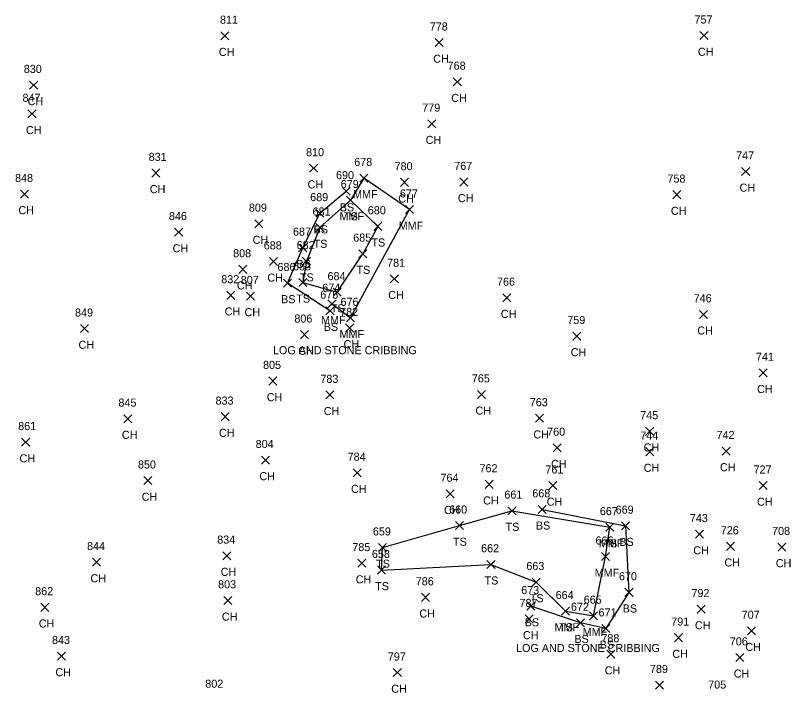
# Model space of a CAD drawing. Extents: x 1885914 to 1887218, y 756253 to 760620.
# Drawn here: x 1886841 to 1887033.2, y 759954.5 to 760121.7 of the extents above; entities that cross this region are included whole.
import ezdxf

# ---------------------------------------------------------------- set-up
doc = ezdxf.new("R2010")
doc.units = 0
for name, color, linetype in [('L_A', 7, 'Continuous'), ('L_C', 7, 'Continuous'), ('L_I', 7, 'Continuous'), ('L_TIC', 7, 'Continuous'), ('LDEFAULT', 7, 'Continuous'), ('LELB', 7, 'Continuous')]:
    doc.layers.add(name, color=color, linetype=linetype)

msp = doc.modelspace()

# ---------------------------------------------------------------- linework, layer by layer
at = {"layer": 'L_TIC'}
for points in [[(1887010.77, 760115.74), (1887012.77, 760117.74)], [(1887012.77, 760115.74), (1887010.77, 760117.74)], [(1886891.98, 760115.7), (1886893.98, 760117.7)], [(1886893.98, 760115.7), (1886891.98, 760117.7)], [(1886945.13, 760114.01), (1886947.13, 760116.01)], [(1886947.13, 760114.01), (1886945.13, 760116.01)], [(1886949.61, 760104.28), (1886951.61, 760106.28)], [(1886951.61, 760104.28), (1886949.61, 760106.28)], [(1886844.55, 760103.48), (1886846.55, 760105.48)], [(1886846.55, 760103.48), (1886844.55, 760105.48)], [(1886844.14, 760096.31), (1886846.14, 760098.31)], [(1886846.14, 760096.31), (1886844.14, 760098.31)], [(1886943.27, 760093.87), (1886945.27, 760095.87)], [(1886945.27, 760093.87), (1886943.27, 760095.87)], [(1886874.87, 760081.65), (1886876.87, 760083.65)], [(1886876.87, 760081.65), (1886874.87, 760083.65)], [(1886913.98, 760082.82), (1886915.98, 760084.82)], [(1886915.98, 760082.82), (1886913.98, 760084.82)], [(1887021.1, 760082.02), (1887023.1, 760084.02)], [(1887023.1, 760082.02), (1887021.1, 760084.02)], [(1886926.45, 760080.4), (1886928.45, 760082.4)], [(1886928.45, 760080.4), (1886926.45, 760082.4)], [(1886936.5, 760079.33), (1886938.5, 760081.33)], [(1886938.5, 760079.33), (1886936.5, 760081.33)], [(1886951.25, 760079.42), (1886953.25, 760081.42)], [(1886953.25, 760079.42), (1886951.25, 760081.42)], [(1886842.29, 760076.43), (1886844.29, 760078.43)], [(1886844.29, 760076.43), (1886842.29, 760078.43)], [(1886922.01, 760077.13), (1886924.01, 760079.13)], [(1886924.01, 760077.13), (1886922.01, 760079.13)], [(1887004.07, 760076.27), (1887006.07, 760078.27)], [(1887006.07, 760076.27), (1887004.07, 760078.27)], [(1886923.1, 760074.91), (1886925.1, 760076.91)], [(1886925.1, 760074.91), (1886923.1, 760076.91)], [(1886923.1, 760074.91), (1886925.1, 760076.91)], [(1886925.1, 760074.91), (1886923.1, 760076.91)], [(1886923.1, 760074.91), (1886925.1, 760076.91)], [(1886925.1, 760074.91), (1886923.1, 760076.91)], [(1886915.53, 760071.66), (1886917.53, 760073.66)], [(1886917.53, 760071.66), (1886915.53, 760073.66)], [(1886937.78, 760072.57), (1886939.78, 760074.57)], [(1886939.78, 760072.57), (1886937.78, 760074.57)], [(1886900.37, 760069.06), (1886902.37, 760071.06)], [(1886902.37, 760069.06), (1886900.37, 760071.06)], [(1886915.55, 760068.09), (1886917.55, 760070.09)], [(1886917.55, 760068.09), (1886915.55, 760070.09)], [(1886929.89, 760068.41), (1886931.89, 760070.41)], [(1886931.89, 760068.41), (1886929.89, 760070.41)], [(1886880.51, 760066.97), (1886882.51, 760068.97)], [(1886882.51, 760066.97), (1886880.51, 760068.97)], [(1886911.26, 760063.1), (1886913.26, 760065.1)], [(1886913.26, 760063.1), (1886911.26, 760065.1)], [(1886926.2, 760061.62), (1886928.2, 760063.62)], [(1886928.2, 760061.62), (1886926.2, 760063.62)], [(1886926.2, 760061.62), (1886928.2, 760063.62)], [(1886928.2, 760061.62), (1886926.2, 760063.62)], [(1886904.01, 760059.69), (1886906.01, 760061.69)], [(1886906.01, 760059.69), (1886904.01, 760061.69)], [(1886912.17, 760059.76), (1886914.17, 760061.76)], [(1886914.17, 760059.76), (1886912.17, 760061.76)], [(1886896.45, 760057.75), (1886898.45, 760059.75)], [(1886898.45, 760057.75), (1886896.45, 760059.75)], [(1886907.47, 760054.34), (1886909.47, 760056.34)], [(1886909.47, 760054.34), (1886907.47, 760056.34)], [(1886911.27, 760054.48), (1886913.27, 760056.48)], [(1886913.27, 760054.48), (1886911.27, 760056.48)], [(1886933.99, 760055.39), (1886935.99, 760057.39)], [(1886935.99, 760055.39), (1886933.99, 760057.39)], [(1886893.43, 760051.3), (1886895.43, 760053.3)], [(1886895.43, 760051.3), (1886893.43, 760053.3)], [(1886898.34, 760051.11), (1886900.34, 760053.11)], [(1886900.34, 760051.11), (1886898.34, 760053.11)], [(1886919.82, 760052.05), (1886921.82, 760054.05)], [(1886921.82, 760052.05), (1886919.82, 760054.05)], [(1886961.91, 760050.69), (1886963.91, 760052.69)], [(1886963.91, 760050.69), (1886961.91, 760052.69)], [(1886918.53, 760049.2), (1886920.53, 760051.2)], [(1886920.53, 760049.2), (1886918.53, 760051.2)], [(1886918.03, 760047.47), (1886920.03, 760049.47)], [(1886920.03, 760047.47), (1886918.03, 760049.47)], [(1886918.03, 760047.47), (1886920.03, 760049.47)], [(1886920.03, 760047.47), (1886918.03, 760049.47)], [(1887010.62, 760046.57), (1887012.62, 760048.57)], [(1887012.62, 760046.57), (1887010.62, 760048.57)], [(1886923.11, 760045.68), (1886925.11, 760047.68)], [(1886925.11, 760045.68), (1886923.11, 760047.68)], [(1886857.18, 760043.03), (1886859.18, 760045.03)], [(1886859.18, 760043.03), (1886857.18, 760045.03)], [(1886922.91, 760043.19), (1886924.91, 760045.19)], [(1886924.91, 760043.19), (1886922.91, 760045.19)], [(1886911.68, 760041.53), (1886913.68, 760043.53)], [(1886913.68, 760041.53), (1886911.68, 760043.53)], [(1886979.25, 760041.18), (1886981.25, 760043.18)], [(1886981.25, 760041.18), (1886979.25, 760043.18)], [(1887025.45, 760032.05), (1887027.45, 760034.05)], [(1887027.45, 760032.05), (1887025.45, 760034.05)], [(1886903.87, 760030.03), (1886905.87, 760032.03)], [(1886905.87, 760030.03), (1886903.87, 760032.03)], [(1886918, 760026.57), (1886920, 760028.57)], [(1886920, 760026.57), (1886918, 760028.57)], [(1886955.62, 760026.69), (1886957.62, 760028.69)], [(1886957.62, 760026.69), (1886955.62, 760028.69)], [(1886867.93, 760020.68), (1886869.93, 760022.68)], [(1886869.93, 760020.68), (1886867.93, 760022.68)], [(1886892.02, 760021.18), (1886894.02, 760023.18)], [(1886894.02, 760021.18), (1886892.02, 760023.18)], [(1886969.99, 760020.78), (1886971.99, 760022.78)], [(1886971.99, 760020.78), (1886969.99, 760022.78)], [(1886997.31, 760017.55), (1886999.31, 760019.55)], [(1886999.31, 760017.55), (1886997.31, 760019.55)], [(1886842.56, 760014.85), (1886844.56, 760016.85)], [(1886844.56, 760014.85), (1886842.56, 760016.85)], [(1886974.38, 760013.46), (1886976.38, 760015.46)], [(1886976.38, 760013.46), (1886974.38, 760015.46)], [(1886997.34, 760012.5), (1886999.34, 760014.5)], [(1886999.34, 760012.5), (1886997.34, 760014.5)], [(1887016.24, 760012.64), (1887018.24, 760014.64)], [(1887018.24, 760012.64), (1887016.24, 760014.64)], [(1886902.04, 760010.41), (1886904.04, 760012.41)], [(1886904.04, 760010.41), (1886902.04, 760012.41)], [(1886924.78, 760007.26), (1886926.78, 760009.26)], [(1886926.78, 760007.26), (1886924.78, 760009.26)], [(1886872.85, 760005.32), (1886874.85, 760007.32)], [(1886874.85, 760005.32), (1886872.85, 760007.32)], [(1886957.52, 760004.39), (1886959.52, 760006.39)], [(1886959.52, 760004.39), (1886957.52, 760006.39)], [(1886973.29, 760004.08), (1886975.29, 760006.08)], [(1886975.29, 760004.08), (1886973.29, 760006.08)], [(1887025.43, 760004.08), (1887027.43, 760006.08)], [(1887027.43, 760004.08), (1887025.43, 760006.08)], [(1886947.84, 760002.03), (1886949.84, 760004.03)], [(1886949.84, 760002.03), (1886947.84, 760004.03)], [(1886963.16, 759997.85), (1886965.16, 759999.85)], [(1886965.16, 759997.85), (1886963.16, 759999.85)], [(1886970.65, 759998.17), (1886972.65, 760000.17)], [(1886972.65, 759998.17), (1886970.65, 760000.17)], [(1886950.13, 759994.15), (1886952.13, 759996.15)], [(1886952.13, 759994.15), (1886950.13, 759996.15)], [(1886987.41, 759993.74), (1886989.41, 759995.74)], [(1886989.41, 759993.74), (1886987.41, 759995.74)], [(1886987.41, 759993.74), (1886989.41, 759995.74)], [(1886989.41, 759993.74), (1886987.41, 759995.74)], [(1886991.33, 759994.11), (1886993.33, 759996.11)], [(1886993.33, 759994.11), (1886991.33, 759996.11)], [(1887009.63, 759992.02), (1887011.63, 759994.02)], [(1887011.63, 759992.02), (1887009.63, 759994.02)], [(1887017.35, 759989.01), (1887019.35, 759991.01)], [(1887019.35, 759989.01), (1887017.35, 759991.01)], [(1886931.08, 759988.71), (1886933.08, 759990.71)], [(1886933.08, 759988.71), (1886931.08, 759990.71)], [(1887030.09, 759988.83), (1887032.09, 759990.83)], [(1887032.09, 759988.83), (1887030.09, 759990.83)], [(1886860.15, 759985.08), (1886862.15, 759987.08)], [(1886862.15, 759985.08), (1886860.15, 759987.08)], [(1886892.43, 759986.68), (1886894.43, 759988.68)], [(1886894.43, 759986.68), (1886892.43, 759988.68)], [(1886986.38, 759986.46), (1886988.38, 759988.46)], [(1886988.38, 759986.46), (1886986.38, 759988.46)], [(1886925.93, 759984.82), (1886927.93, 759986.82)], [(1886927.93, 759984.82), (1886925.93, 759986.82)], [(1886930.83, 759983.13), (1886932.83, 759985.13)], [(1886932.83, 759983.13), (1886930.83, 759985.13)], [(1886930.83, 759983.13), (1886932.83, 759985.13)], [(1886932.83, 759983.13), (1886930.83, 759985.13)], [(1886957.95, 759984.53), (1886959.95, 759986.53)], [(1886959.95, 759984.53), (1886957.95, 759986.53)], [(1886969.18, 759980.13), (1886971.18, 759982.13)], [(1886971.18, 759980.13), (1886969.18, 759982.13)], [(1886992.17, 759977.59), (1886994.17, 759979.59)], [(1886994.17, 759977.59), (1886992.17, 759979.59)], [(1886892.72, 759975.58), (1886894.72, 759977.58)], [(1886894.72, 759975.58), (1886892.72, 759977.58)], [(1886941.71, 759976.35), (1886943.71, 759978.35)], [(1886943.71, 759976.35), (1886941.71, 759978.35)], [(1886847.34, 759973.87), (1886849.34, 759975.87)], [(1886849.34, 759973.87), (1886847.34, 759975.87)], [(1886967.86, 759974.15), (1886969.86, 759976.15)], [(1886969.86, 759974.15), (1886967.86, 759976.15)], [(1886976.44, 759972.93), (1886978.44, 759974.93)], [(1886978.44, 759972.93), (1886976.44, 759974.93)], [(1886976.44, 759972.93), (1886978.44, 759974.93)], [(1886978.44, 759972.93), (1886976.44, 759974.93)], [(1886983.39, 759971.78), (1886985.39, 759973.78)], [(1886985.39, 759971.78), (1886983.39, 759973.78)], [(1887010.04, 759973.41), (1887012.04, 759975.41)], [(1887012.04, 759973.41), (1887010.04, 759975.41)], [(1886967.39, 759970.97), (1886969.39, 759972.97)], [(1886969.39, 759970.97), (1886967.39, 759972.97)], [(1886980.18, 759970.02), (1886982.18, 759972.02)], [(1886982.18, 759970.02), (1886980.18, 759972.02)], [(1886986.46, 759968.61), (1886988.46, 759970.61)], [(1886988.46, 759968.61), (1886986.46, 759970.61)], [(1887022.56, 759968.04), (1887024.56, 759970.04)], [(1887024.56, 759968.04), (1887022.56, 759970.04)], [(1887004.44, 759966.34), (1887006.44, 759968.34)], [(1887006.44, 759966.34), (1887004.44, 759968.34)], [(1886987.69, 759962.23), (1886989.69, 759964.23)], [(1886989.69, 759962.23), (1886987.69, 759964.23)], [(1886851.46, 759961.77), (1886853.46, 759963.77)], [(1886853.46, 759961.77), (1886851.46, 759963.77)], [(1887019.66, 759961.43), (1887021.66, 759963.43)], [(1887021.66, 759961.43), (1887019.66, 759963.43)], [(1886934.73, 759957.67), (1886936.73, 759959.67)], [(1886936.73, 759957.67), (1886934.73, 759959.67)], [(1886999.74, 759954.58), (1887001.74, 759956.58)], [(1887001.74, 759954.58), (1886999.74, 759956.58)]]:
    msp.add_lwpolyline(points, dxfattribs=at)
at = {"layer": 'LDEFAULT'}
for points in [[(1886919.53, 760050.2), (1886924.11, 760046.68), (1886938.78, 760073.57), (1886927.45, 760081.4), (1886924.1, 760075.91)], [(1886977.44, 759973.93), (1886984.39, 759972.78), (1886987.38, 759987.46), (1886988.41, 759994.74)]]:
    msp.add_lwpolyline(points, dxfattribs=at)
at = {"layer": 'LELB'}
for points in [[(1886919.03, 760048.47), (1886908.47, 760055.34), (1886912.26, 760064.1), (1886916.53, 760072.66), (1886923.01, 760078.13)], [(1886924.1, 760075.91), (1886916.55, 760069.09), (1886913.17, 760060.76), (1886912.27, 760055.48), (1886920.82, 760053.05), (1886927.2, 760062.62)], [(1886924.1, 760075.91), (1886930.89, 760069.41), (1886927.2, 760062.62)], [(1886931.83, 759984.13), (1886932.08, 759989.71), (1886951.13, 759995.15), (1886964.16, 759998.85), (1886988.41, 759994.74)], [(1886971.65, 759999.17), (1886992.33, 759995.11), (1886993.17, 759978.59), (1886987.46, 759969.61), (1886981.18, 759971.02), (1886968.86, 759975.15)], [(1886931.83, 759984.13), (1886958.95, 759985.53), (1886970.18, 759981.13), (1886977.44, 759973.93)]]:
    msp.add_lwpolyline(points, dxfattribs=at)

# ---------------------------------------------------------------- texts
at = {"layer": 'L_A'}
for s, p in [('CH', (1886891.47, 760111.7)), ('CH', (1886944.62, 760110.01)), ('CH', (1887010.26, 760111.74)), ('CH', (1886844.04, 760099.48)), ('CH', (1886949.1, 760100.28)), ('CH', (1886843.63, 760092.31)), ('CH', (1886942.75, 760089.87)), ('CH', (1886874.35, 760077.65)), ('CH', (1886913.47, 760078.82)), ('CH', (1887020.59, 760078.02)), ('MMF', (1886924.74, 760076.4)), ('CH', (1886950.74, 760075.42)), ('CH', (1886935.98, 760075.33)), ('CH', (1886841.78, 760072.43)), ('BS', (1886921.45, 760073.13)), ('CH', (1887003.56, 760072.27)), ('MMF', (1886921.39, 760070.91)), ('TS', (1886922.51, 760070.91)), ('TS', (1886922.51, 760070.91)), ('BS', (1886914.97, 760067.66)), ('MMF', (1886936.06, 760068.57)), ('CH', (1886899.86, 760065.06)), ('TS', (1886914.96, 760064.09)), ('TS', (1886929.3, 760064.41)), ('CH', (1886880, 760062.97)), ('BS', (1886910.7, 760059.1)), ('TS', (1886925.61, 760057.62)), ('TS', (1886925.61, 760057.62)), ('CH', (1886903.5, 760055.69)), ('TS', (1886911.58, 760055.76)), ('CH', (1886895.94, 760053.75)), ('TS', (1886910.68, 760050.48)), ('CH', (1886933.48, 760051.39)), ('BS', (1886906.91, 760050.34)), ('CH', (1886892.92, 760047.3)), ('CH', (1886897.83, 760047.11)), ('TS', (1886919.23, 760048.05)), ('CH', (1886961.4, 760046.69)), ('MMF', (1886916.81, 760045.2)), ('BS', (1886917.47, 760043.47)), ('BS', (1886917.47, 760043.47)), ('MMF', (1886921.4, 760041.68)), ('CH', (1887010.11, 760042.57)), ('CH', (1886856.67, 760039.03)), ('CH', (1886922.4, 760039.19)), ('CH', (1886911.17, 760037.53)), ('CH', (1886978.74, 760037.18)), ('CH', (1887024.93, 760028.05)), ('CH', (1886903.36, 760026.03)), ('CH', (1886917.49, 760022.57)), ('CH', (1886955.11, 760022.69)), ('CH', (1886867.42, 760016.68)), ('CH', (1886891.5, 760017.18)), ('CH', (1886969.48, 760016.78)), ('CH', (1886996.8, 760013.55)), ('CH', (1886842.04, 760010.85)), ('CH', (1886973.86, 760009.46)), ('CH', (1886996.83, 760008.5)), ('CH', (1887015.73, 760008.64)), ('CH', (1886901.53, 760006.41)), ('CH', (1886924.26, 760003.26)), ('CH', (1886872.34, 760001.32)), ('CH', (1886957.01, 760000.39)), ('CH', (1886972.77, 760000.08)), ('CH', (1887024.92, 760000.08)), ('CH', (1886947.32, 759998.03)), ('TS', (1886962.57, 759993.85)), ('BS', (1886970.09, 759994.17)), ('TS', (1886949.54, 759990.15)), ('MMF', (1886985.69, 759989.74)), ('TS', (1886986.82, 759989.74)), ('BS', (1886990.77, 759990.11)), ('CH', (1887009.12, 759988.02)), ('TS', (1886930.49, 759984.71)), ('CH', (1887016.84, 759985.01)), ('CH', (1887029.58, 759984.83)), ('CH', (1886891.92, 759982.68)), ('MMF', (1886984.66, 759982.46)), ('CH', (1886859.64, 759981.08)), ('CH', (1886925.42, 759980.82)), ('TS', (1886957.36, 759980.53)), ('TS', (1886930.23, 759979.13)), ('TS', (1886930.23, 759979.13)), ('TS', (1886968.59, 759976.13)), ('BS', (1886991.61, 759973.59)), ('CH', (1886892.21, 759971.58)), ('CH', (1886941.2, 759972.35)), ('CH', (1886846.82, 759969.87)), ('BS', (1886967.3, 759970.15)), ('MMF', (1886974.72, 759968.93)), ('TS', (1886975.85, 759968.93)), ('MMF', (1886981.68, 759967.78)), ('CH', (1887009.52, 759969.41)), ('CH', (1886966.88, 759966.97)), ('BS', (1886979.63, 759966.02)), ('BS', (1886985.9, 759964.61)), ('CH', (1887022.05, 759964.04)), ('CH', (1887003.93, 759962.34)), ('CH', (1886987.17, 759958.23)), ('CH', (1886850.95, 759957.77)), ('CH', (1887019.15, 759957.43)), ('CH', (1886934.22, 759953.67))]:
    msp.add_text(s, height=2, dxfattribs=at).set_placement(p)
at = {"layer": 'L_C'}
for p in [(1886904.89, 760037.68), (1886965.17, 759963.78)]:
    msp.add_text('LOG AND STONE CRIBBING', height=2, dxfattribs=at).set_placement(p)
at = {"layer": 'L_I'}
for s, p in [('811', (1886891.75, 760119.7)), ('757', (1887009.41, 760119.74)), ('778', (1886943.77, 760118.01)), ('768', (1886948.2, 760108.28)), ('830', (1886843.1, 760107.48)), ('847', (1886842.78, 760100.31)), ('779', (1886941.9, 760097.87)), ('831', (1886874.07, 760085.65)), ('810', (1886913.1, 760086.82)), ('747', (1887019.74, 760086.02)), ('678', (1886925.04, 760084.4)), ('780', (1886935.05, 760083.33)), ('767', (1886949.84, 760083.42)), ('690', (1886920.52, 760081.13)), ('848', (1886840.93, 760080.43)), ('758', (1887002.71, 760080.27)), ('679', (1886921.68, 760078.91)), ('679', (1886921.68, 760078.91)), ('679', (1886921.68, 760078.91)), ('689', (1886914.12, 760075.66)), ('677', (1886936.37, 760076.57)), ('809', (1886898.92, 760073.06)), ('681', (1886914.7, 760072.09)), ('680', (1886928.4, 760072.41)), ('846', (1886879.09, 760070.97)), ('687', (1886909.85, 760067.1)), ('685', (1886924.79, 760065.62)), ('685', (1886924.79, 760065.62)), ('688', (1886902.6, 760063.69)), ('682', (1886910.76, 760063.76)), ('808', (1886895.01, 760061.75)), ('686', (1886906.01, 760058.34)), ('683', (1886909.86, 760058.48)), ('781', (1886933.19, 760059.39)), ('832', (1886892.07, 760055.3)), ('807', (1886896.9, 760055.11)), ('684', (1886918.41, 760056.05)), ('766', (1886960.44, 760054.69)), ('674', (1886917.12, 760053.2)), ('675', (1886916.62, 760051.47)), ('675', (1886916.62, 760051.47)), ('746', (1887009.21, 760050.57)), ('676', (1886921.65, 760049.68)), ('849', (1886855.81, 760047.03)), ('782', (1886921.55, 760047.19)), ('806', (1886910.19, 760045.53)), ('759', (1886977.88, 760045.18)), ('741', (1887024.65, 760036.05)), ('805', (1886902.43, 760034.03)), ('783', (1886916.64, 760030.57)), ('765', (1886954.21, 760030.69)), ('845', (1886866.57, 760024.68)), ('833', (1886890.65, 760025.18)), ('763', (1886968.58, 760024.78)), ('745', (1886995.95, 760021.55)), ('861', (1886841.71, 760018.85)), ('760', (1886972.88, 760017.46)), ('744', (1886995.98, 760016.5)), ('742', (1887014.88, 760016.64)), ('804', (1886900.6, 760014.41)), ('784', (1886923.41, 760011.26)), ('850', (1886871.41, 760009.32)), ('762', (1886956.11, 760008.39)), ('761', (1886972.44, 760008.08)), ('727', (1887024.07, 760008.08)), ('764', (1886946.43, 760006.03)), ('661', (1886962.27, 760001.85)), ('668', (1886969.2, 760002.17)), ('660', (1886948.59, 759998.15)), ('667', (1886985.95, 759997.74)), ('667', (1886985.95, 759997.74)), ('669', (1886989.86, 759998.11)), ('743', (1887008.27, 759996.02)), ('659', (1886929.67, 759992.71)), ('726', (1887015.93, 759993.01)), ('708', (1887028.65, 759992.83)), ('844', (1886858.79, 759989.08)), ('834', (1886891.07, 759990.68)), ('666', (1886984.87, 759990.46)), ('785', (1886924.57, 759988.82)), ('658', (1886929.42, 759987.13)), ('658', (1886929.42, 759987.13)), ('662', (1886956.49, 759988.53)), ('663', (1886967.72, 759984.13)), ('670', (1886990.68, 759981.59)), ('803', (1886891.28, 759979.58)), ('786', (1886940.29, 759980.35)), ('862', (1886845.93, 759977.87)), ('673', (1886966.45, 759978.15)), ('792', (1887008.67, 759977.41)), ('664', (1886974.98, 759976.93)), ('664', (1886974.98, 759976.93)), ('665', (1886981.94, 759975.78)), ('787', (1886966.03, 759974.97)), ('672', (1886978.78, 759974.02)), ('671', (1886985.62, 759972.61)), ('707', (1887021.12, 759972.04)), ('791', (1887003.65, 759970.34)), ('788', (1886986.32, 759966.23)), ('843', (1886850.1, 759965.77)), ('706', (1887018.17, 759965.43)), ('797', (1886933.37, 759961.67)), ('789', (1886998.37, 759958.58)), ('802', (1886888.11, 759954.92)), ('705', (1887012.81, 759954.7))]:
    msp.add_text(s, height=2, dxfattribs=at).set_placement(p)

doc.saveas('drawing.dxf')
